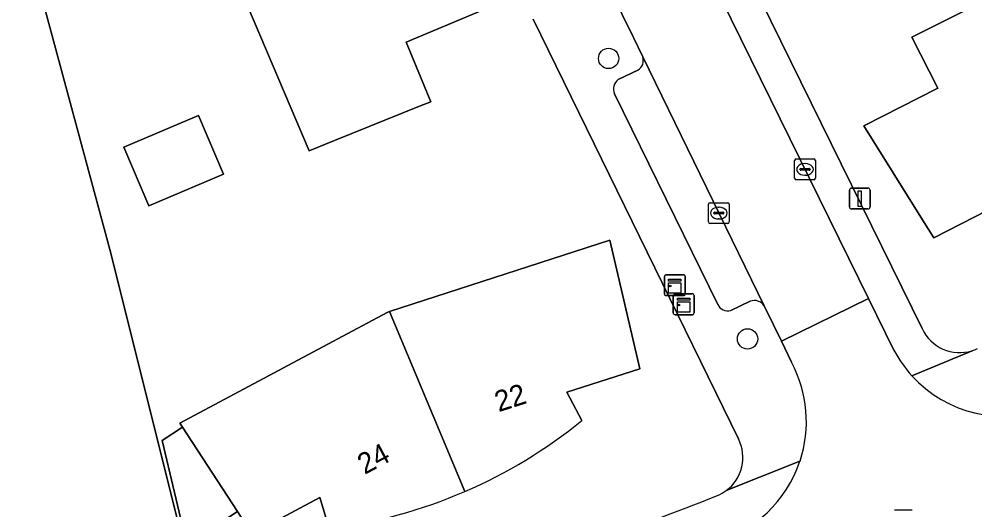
# Model space of a CAD drawing. Extents: x 159053 to 160042, y 380449 to 381423.
# Drawn here: x 159407.8 to 159453.83, y 380869.78 to 380893.4 of the extents above; entities that cross this region are included whole.
import ezdxf

# ---------------------------------------------------------------- set-up
doc = ezdxf.new("R2010")
doc.units = 0
for name, color, linetype in [('IMGEO_Boom', 7, 'Continuous'), ('IMGEO_Erf', 7, 'Continuous'), ('IMGEO_Groenvoorziening', 7, 'Continuous'), ('IMGEO_Kast', 7, 'Continuous'), ('IMGEO_Kolk', 7, 'Continuous'), ('IMGEO_Lichtmast', 7, 'Continuous'), ('IMGEO_Pand', 7, 'Continuous'), ('IMGEO_Pand_nummerreeks', 7, 'Continuous'), ('IMGEO_Parkeervlak_open', 7, 'Continuous'), ('IMGEO_Rijbaan_lokaal_open', 7, 'Continuous'), ('IMGEO_Rioolput', 7, 'Continuous'), ('IMGEO_Voetpad_open', 7, 'Continuous')]:
    doc.layers.add(name, color=color, linetype=linetype)

msp = doc.modelspace()

# ---------------------------------------------------------------- linework, layer by layer
at = {"layer": 'IMGEO_Boom'}
for centre in [(159436.189, 380891.507), (159442.881, 380878.007)]:
    msp.add_circle(centre, 0.489, dxfattribs=at)
at = {"layer": 'IMGEO_Erf'}
for points in [[(159408.965, 380964.525), (159406.59, 380964.068), (159401.237, 380962.888), (159388.835, 380959.508), (159387.783, 380959.221), (159399.303, 380929.877), (159412.172, 380882.306), (159415.898, 380867.448), (159416.608, 380864.597), (159416.656, 380864.403), (159417.452, 380863.784), (159418.791, 380864.086), (159429.053, 380866.431)], [(159418.369, 380924.458), (159420.347, 380917.887), (159416.517, 380916.735), (159417.526, 380913.88), (159418.591, 380910.865), (159422.277, 380912.418), (159424.886, 380906.225), (159427.441, 380900.163), (159430.109, 380893.831), (159426.433, 380892.288), (159427.633, 380889.421), (159427.088, 380889.202), (159422.993, 380887.56), (159421.762, 380887.066), (159417.932, 380896.096), (159420.125, 380897.081), (159417.551, 380903.138), (159415.055, 380909.013), (159413.002, 380908.175), (159411.697, 380911.8), (159410.451, 380915.26), (159409.474, 380915.644), (159407.916, 380920.993)], [(159452.048, 380890.082), (159450.799, 380892.535), (159457.704, 380896), (159468.395, 380899.243), (159469.193, 380896.611), (159480.383, 380897.975), (159480.699, 380888.61)], [(159442.282, 380897.463), (159442.043, 380897.312), (159451.283, 380878.508)], [(159442.437, 380873.196), (159432.55, 380893.397)], [(159455.564, 380883.052), (159455.107, 380884.541), (159451.847, 380882.876), (159451.307, 380883.741), (159448.483, 380888.267), (159452.048, 380890.082)], [(159425.64, 380879.326), (159436.255, 380882.753), (159437.692, 380876.57), (159434.182, 380875.448), (159434.903, 380874.082)], [(159422.733, 380868.891), (159422.278, 380870.382), (159419, 380868.631), (159418.308, 380869.696), (159415.88, 380868.118), (159414.68, 380873.123), (159415.665, 380873.763), (159415.538, 380873.959), (159425.516, 380879.286), (159425.64, 380879.326)]]:
    msp.add_lwpolyline(points, dxfattribs=at)
msp.add_lwpolyline([(159417.636, 380885.929), (159414.047, 380884.406), (159412.844, 380887.241), (159416.433, 380888.764)], close=True, dxfattribs=at)
for centre, radius, start, end in [((159453.103, 380879.361), 2.01, 205.1136, 287.1951), ((159453.088, 380879.391), 2.043, 287.3366, 295.2901), ((159419.773, 380892.695), 23.986, 293.3032, 309.107), ((159440.702, 380872.294), 1.956, 306.0218, 27.474), ((159419.759, 380892.736), 24.03, 277.1081, 293.2937), ((159440.742, 380872.215), 1.868, 291.7055, 306.4501), ((159407.192, 380954.245), 90.494, 283.97973, 292.23359)]:
    msp.add_arc(centre, radius, start, end, dxfattribs=at)
at = {"layer": 'IMGEO_Groenvoorziening'}
msp.add_lwpolyline([(159339.63, 380858.444), (159343.386, 380845.223), (159357.481, 380849.075), (159416.608, 380864.597), (159415.898, 380867.448), (159412.172, 380882.306), (159399.303, 380929.877)], dxfattribs=at)
at = {"layer": 'IMGEO_Kast'}
for p, q in [((159438.876, 380880.165), (159438.876, 380881.006)), ((159438.876, 380881.006), (159438.876, 380880.165)), ((159438.951, 380881.09), (159439.792, 380881.09)), ((159439.792, 380881.09), (159438.951, 380881.09)), ((159439.876, 380881.015), (159439.876, 380880.174)), ((159439.876, 380880.174), (159439.876, 380881.015)), ((159439.801, 380880.09), (159438.96, 380880.09)), ((159438.96, 380880.09), (159439.801, 380880.09)), ((159439.304, 380879.25), (159439.304, 380880.091)), ((159439.304, 380880.091), (159439.304, 380879.25)), ((159439.379, 380880.175), (159440.22, 380880.175)), ((159440.22, 380880.175), (159439.379, 380880.175)), ((159440.304, 380880.1), (159440.304, 380879.259)), ((159440.304, 380879.259), (159440.304, 380880.1)), ((159440.229, 380879.175), (159439.388, 380879.175)), ((159439.388, 380879.175), (159440.229, 380879.175))]:
    msp.add_line(p, q, dxfattribs=at)
for points in [[(159439.071, 380880.88), (159439.671, 380880.88), (159439.671, 380880.795), (159439.071, 380880.795), (159439.071, 380880.88)], [(159439.071, 380880.705), (159439.671, 380880.705), (159439.671, 380880.216), (159439.071, 380880.216), (159439.071, 380880.705)], [(159439.499, 380879.965), (159440.099, 380879.965), (159440.099, 380879.88), (159439.499, 380879.88), (159439.499, 380879.965)], [(159439.499, 380879.79), (159440.099, 380879.79), (159440.099, 380879.301), (159439.499, 380879.301), (159439.499, 380879.79)]]:
    msp.add_lwpolyline(points, dxfattribs=at)
for centre in [(159439.155, 380880.554), (159439.583, 380879.639)]:
    msp.add_circle(centre, 0.0377, dxfattribs=at)
for centre, start, end in [((159438.954, 380881.012), 92.4484, 184.2845), ((159438.954, 380881.012), 92.4484, 184.2845), ((159439.798, 380881.012), 2.4484, 94.2845), ((159439.798, 380881.012), 2.4484, 94.2845), ((159438.954, 380880.168), 182.4484, 274.2845), ((159438.954, 380880.168), 182.4484, 274.2845), ((159439.382, 380880.097), 92.4484, 184.2845), ((159439.382, 380880.097), 92.4484, 184.2845), ((159439.798, 380880.168), 272.4484, 4.2845), ((159439.798, 380880.168), 272.4484, 4.2845), ((159440.226, 380880.097), 2.4484, 94.2845), ((159440.226, 380880.097), 2.4484, 94.2845), ((159439.382, 380879.253), 182.4484, 274.2845), ((159439.382, 380879.253), 182.4484, 274.2845), ((159440.226, 380879.253), 272.4484, 4.2845), ((159440.226, 380879.253), 272.4484, 4.2845)]:
    msp.add_arc(centre, 0.0779, start, end, dxfattribs=at)
at = {"layer": 'IMGEO_Kolk'}
for p, q in [((159445.147, 380885.741), (159445.147, 380886.593)), ((159445.222, 380886.667), (159446.074, 380886.667)), ((159445.635, 380886.447), (159445.66, 380886.447)), ((159446.148, 380886.593), (159446.148, 380885.741)), ((159445.406, 380886.161), (159445.406, 380886.173)), ((159445.844, 380886.124), (159445.446, 380886.124)), ((159445.449, 380886.21), (159445.847, 380886.21)), ((159445.658, 380885.887), (159445.633, 380885.887)), ((159445.89, 380886.173), (159445.89, 380886.161)), ((159446.074, 380885.667), (159445.222, 380885.667)), ((159440.997, 380883.637), (159440.997, 380884.489)), ((159441.072, 380884.563), (159441.924, 380884.563)), ((159441.998, 380884.489), (159441.998, 380883.637)), ((159441.256, 380884.057), (159441.256, 380884.069)), ((159441.694, 380884.02), (159441.296, 380884.02)), ((159441.299, 380884.106), (159441.697, 380884.106)), ((159441.485, 380884.343), (159441.51, 380884.343)), ((159441.74, 380884.069), (159441.74, 380884.057)), ((159441.924, 380883.563), (159441.072, 380883.563)), ((159441.508, 380883.783), (159441.483, 380883.783))]:
    msp.add_line(p, q, dxfattribs=at)
for points in [[(159445.147, 380885.741), (159445.147, 380886.593)], [(159445.222, 380886.667), (159446.074, 380886.667)], [(159446.148, 380886.593), (159446.148, 380885.741)], [(159446.074, 380885.667), (159445.222, 380885.667)], [(159440.997, 380883.637), (159440.997, 380884.489)], [(159441.072, 380884.563), (159441.924, 380884.563)], [(159441.998, 380884.489), (159441.998, 380883.637)], [(159441.924, 380883.563), (159441.072, 380883.563)]]:
    msp.add_lwpolyline(points, dxfattribs=at)
for centre, radius, start, end in [((159445.224, 380886.591), 0.0765, 91.552, 178.448), ((159445.224, 380886.591), 0.0765, 91.552, 178.448), ((159446.072, 380886.591), 0.0765, 1.552, 88.448), ((159446.072, 380886.591), 0.0765, 1.552, 88.448), ((159445.446, 380886.17), 0.0403, 85.8775, 175.7526), ((159445.443, 380886.16), 0.0366, 178.938, 274.7102), ((159445.847, 380886.167), 0.043, 264.8664, 352.4533), ((159445.851, 380886.172), 0.0386, 1.7309, 96.639), ((159445.224, 380885.743), 0.0765, 181.552, 268.448), ((159445.224, 380885.743), 0.0765, 181.552, 268.448), ((159446.072, 380885.743), 0.0765, 271.552, 358.448), ((159446.072, 380885.743), 0.0765, 271.552, 358.448), ((159441.074, 380884.487), 0.0765, 91.552, 178.448), ((159441.074, 380884.487), 0.0765, 91.552, 178.448), ((159441.922, 380884.487), 0.0765, 1.552, 88.448), ((159441.922, 380884.487), 0.0765, 1.552, 88.448), ((159441.296, 380884.066), 0.0403, 85.8775, 175.7526), ((159441.293, 380884.056), 0.0366, 178.938, 274.7102), ((159441.697, 380884.063), 0.043, 264.8664, 352.4533), ((159441.701, 380884.068), 0.0386, 1.7309, 96.639), ((159441.074, 380883.639), 0.0765, 181.552, 268.448), ((159441.074, 380883.639), 0.0765, 181.552, 268.448), ((159441.922, 380883.639), 0.0765, 271.552, 358.448), ((159441.922, 380883.639), 0.0765, 271.552, 358.448)]:
    msp.add_arc(centre, radius, start, end, dxfattribs=at)
for centre, major_axis, ratio, start_param, end_param in [((159445.634, 380886.167), (-0.387, 0.002), 0.722429, 4.712389, 7.853982), ((159445.659, 380886.167), (-0.39, 0.002), 0.717154, 1.570796, 4.712389), ((159441.484, 380884.063), (-0.387, 0.002), 0.722429, 4.712389, 7.853982), ((159441.509, 380884.063), (-0.39, 0.002), 0.717154, 1.570796, 4.712389)]:
    msp.add_ellipse(centre, major_axis=major_axis, ratio=ratio, start_param=start_param, end_param=end_param, dxfattribs=at)
at = {"layer": 'IMGEO_Lichtmast'}
for p, q in [((159447.79, 380884.363), (159447.79, 380885.163)), ((159447.79, 380885.163), (159447.79, 380884.363)), ((159447.89, 380885.263), (159448.68, 380885.263)), ((159448.68, 380885.263), (159447.89, 380885.263)), ((159448.78, 380885.163), (159448.78, 380884.363)), ((159448.78, 380884.363), (159448.78, 380885.163)), ((159448.68, 380884.263), (159447.89, 380884.263)), ((159447.89, 380884.263), (159448.68, 380884.263))]:
    msp.add_line(p, q, dxfattribs=at)
msp.add_lwpolyline([(159448.21, 380885.138), (159448.36, 380885.138), (159448.36, 380884.388), (159448.21, 380884.388), (159448.21, 380885.138)], dxfattribs=at)
for centre, start, end in [((159447.89, 380885.163), 90, 180), ((159447.89, 380885.163), 90, 180), ((159448.68, 380885.163), 0, 90), ((159448.68, 380885.163), 360, 90), ((159447.89, 380884.363), 180, 270), ((159447.89, 380884.363), 180, 270), ((159448.68, 380884.363), 270, 0), ((159448.68, 380884.363), 270, 0)]:
    msp.add_arc(centre, 0.1, start, end, dxfattribs=at)
at = {"layer": 'IMGEO_Pand'}
for points in [[(159420.125, 380897.081), (159417.932, 380896.096), (159421.762, 380887.066), (159422.993, 380887.56), (159427.088, 380889.202), (159427.633, 380889.421), (159426.433, 380892.288), (159430.109, 380893.831), (159427.441, 380900.163)], [(159417.636, 380885.929), (159416.433, 380888.764), (159412.844, 380887.241), (159414.047, 380884.406)], [(159415.665, 380873.763), (159414.68, 380873.123), (159415.88, 380868.118), (159418.308, 380869.696)]]:
    msp.add_lwpolyline(points, close=True, dxfattribs=at)
for points in [[(159462.103, 380884.706), (159458.502, 380893.368), (159457.704, 380896), (159450.799, 380892.535), (159452.048, 380890.082), (159448.483, 380888.267), (159451.307, 380883.741), (159451.847, 380882.876), (159455.107, 380884.541), (159455.564, 380883.052)], [(159434.903, 380874.082), (159434.182, 380875.448), (159437.692, 380876.57), (159436.255, 380882.753), (159425.64, 380879.326), (159429.262, 380870.665)], [(159425.64, 380879.326), (159425.516, 380879.286), (159415.538, 380873.959), (159415.665, 380873.763), (159418.308, 380869.696), (159419, 380868.631), (159422.278, 380870.382), (159422.733, 380868.891)], [(159429.262, 380870.665), (159425.64, 380879.326)]]:
    msp.add_lwpolyline(points, dxfattribs=at)
for centre, radius, start, end in [((159419.773, 380892.695), 23.986, 293.3032, 309.107), ((159419.759, 380892.736), 24.03, 277.1081, 293.2937)]:
    msp.add_arc(centre, radius, start, end, dxfattribs=at)
at = {"layer": 'IMGEO_Parkeervlak_open'}
for points in [[(159443.686, 380879.608), (159437.83, 380891.578)], [(159437.599, 380890.949), (159436.656, 380890.488)], [(159436.477, 380889.801), (159441.443, 380879.669)], [(159442.074, 380879.374), (159443.005, 380879.819)]]:
    msp.add_lwpolyline(points, dxfattribs=at)
for centre, radius, start, end in [((159437.342, 380891.4), 0.519, 299.6385, 20.03), ((159436.953, 380890.044), 0.534, 123.7558, 207.0364), ((159443.212, 380879.284), 0.574, 34.3758, 111.1942), ((159441.928, 380879.884), 0.53, 203.8814, 286.0054)]:
    msp.add_arc(centre, radius, start, end, dxfattribs=at)
at = {"layer": 'IMGEO_Rijbaan_lokaal_open'}
for points in [[(159434.712, 380897.978), (159434.938, 380897.5), (159435.166, 380897.023), (159437.382, 380892.506), (159437.83, 380891.578), (159443.686, 380879.608), (159444.135, 380878.69), (159444.514, 380877.895), (159448.706, 380879.957), (159440.203, 380897.267)], [(159449.928, 380877.47), (159448.706, 380879.957), (159444.514, 380877.895), (159444.997, 380876.883)]]:
    msp.add_lwpolyline(points, dxfattribs=at)
for centre, radius, start, end in [((159455.182, 380880.232), 5.935, 207.7311, 222.2904), ((159439.682, 380874.032), 6.032, 341.6358, 28.2048), ((159455.206, 380880.246), 5.963, 222.2366, 291.8587), ((159439.675, 380874.036), 6.039, 285.0552, 341.6167)]:
    msp.add_arc(centre, radius, start, end, dxfattribs=at)
at = {"layer": 'IMGEO_Rioolput'}
msp.add_line((159449.963, 380869.782), (159450.815, 380869.782), dxfattribs=at)
msp.add_lwpolyline([(159449.963, 380869.782), (159450.815, 380869.782)], dxfattribs=at)
at = {"layer": 'IMGEO_Voetpad_open'}
for points in [[(159437.83, 380891.578), (159437.382, 380892.506), (159435.166, 380897.023), (159434.938, 380897.5), (159434.712, 380897.978)], [(159451.283, 380878.508), (159442.043, 380897.312), (159442.282, 380897.463)], [(159440.203, 380897.267), (159448.706, 380879.957), (159449.928, 380877.47)], [(159432.55, 380893.397), (159442.437, 380873.196)], [(159436.656, 380890.488), (159437.599, 380890.949)], [(159441.443, 380879.669), (159436.477, 380889.801)], [(159443.005, 380879.819), (159442.074, 380879.374)], [(159444.997, 380876.883), (159444.514, 380877.895), (159444.135, 380878.69), (159443.686, 380879.608)], [(159450.791, 380876.238), (159453.697, 380877.441)], [(159453.697, 380877.441), (159450.791, 380876.238)], [(159445.406, 380872.132), (159441.852, 380870.712)], [(159441.852, 380870.712), (159445.406, 380872.132)]]:
    msp.add_lwpolyline(points, dxfattribs=at)
for centre, radius, start, end in [((159437.342, 380891.4), 0.519, 299.6385, 20.03), ((159436.953, 380890.044), 0.534, 123.7558, 207.0364), ((159443.212, 380879.284), 0.574, 34.3758, 111.1942), ((159441.928, 380879.884), 0.53, 203.8814, 286.0054), ((159453.103, 380879.361), 2.01, 205.1136, 287.1951), ((159453.088, 380879.391), 2.043, 287.3366, 295.2901), ((159455.182, 380880.232), 5.935, 207.7311, 222.2904), ((159439.682, 380874.032), 6.032, 341.6358, 28.2048), ((159455.206, 380880.246), 5.963, 222.2366, 291.8587), ((159440.702, 380872.294), 1.956, 306.0218, 27.474), ((159439.675, 380874.036), 6.039, 285.0552, 341.6167), ((159440.742, 380872.215), 1.868, 291.7055, 306.4501), ((159407.192, 380954.245), 90.494, 283.97973, 292.23359)]:
    msp.add_arc(centre, radius, start, end, dxfattribs=at)

# ---------------------------------------------------------------- texts
at = {"layer": 'IMGEO_Pand_nummerreeks'}
for s, rotation, p in [('22', 17.7269, (159430.892, 380874.48)), ('24', 28.1093, (159424.438, 380871.461))]:
    msp.add_text(s, height=1, rotation=rotation, dxfattribs=at).set_placement(p)

doc.saveas('drawing.dxf')
